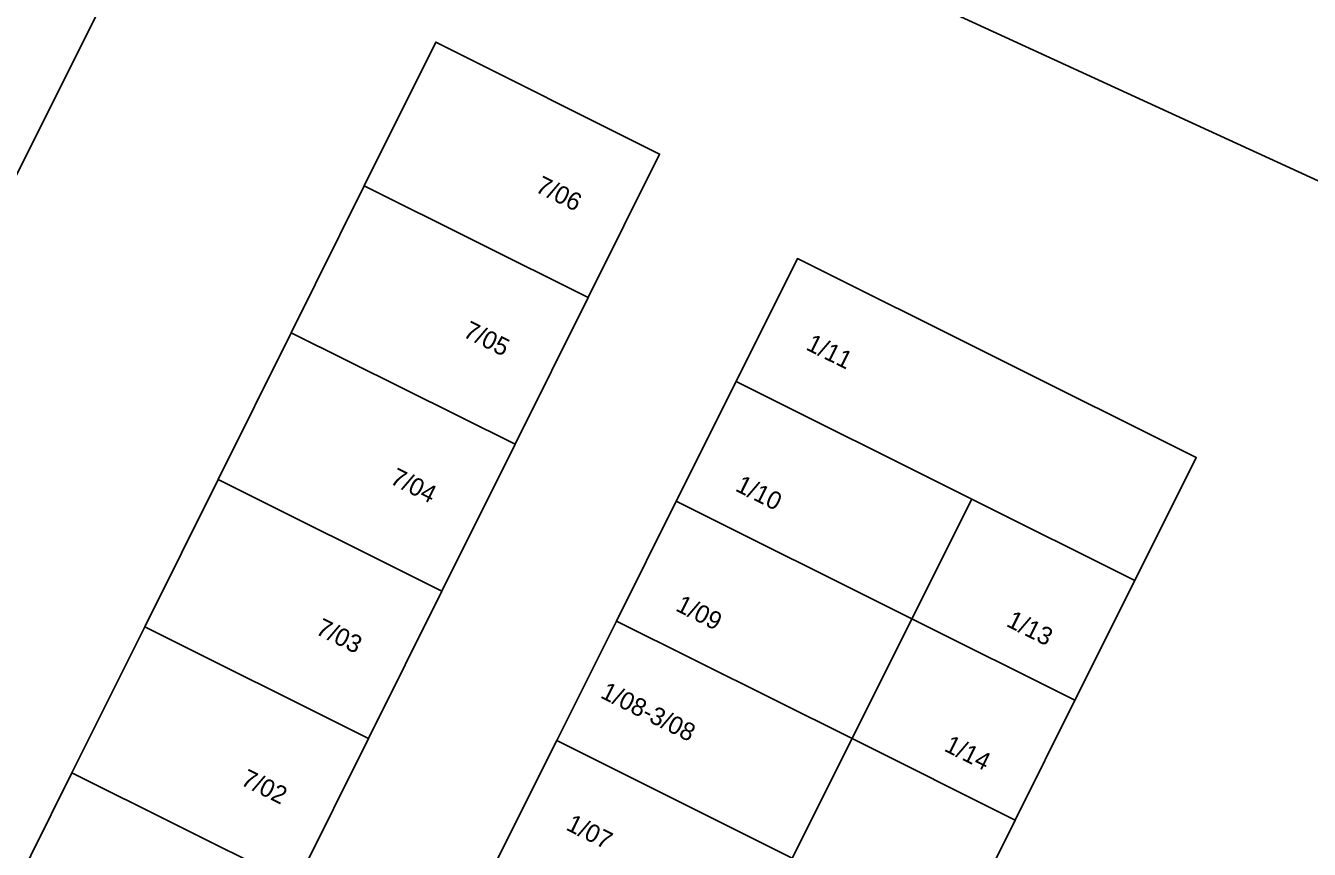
# Model space of a CAD drawing. Extents: x 135999 to 138000, y 396000 to 398501.
# Drawn here: x 136106.9 to 136178.9, y 397811.3 to 397857.5 of the extents above; entities that cross this region are included whole.
import ezdxf

# ---------------------------------------------------------------- set-up
doc = ezdxf.new("R2010")
doc.units = 0
for name, color, linetype in [('gg-anno-huisnummerreeks BGT', 7, 'Continuous'), ('gg-bbg-hoofdgebouw', 7, 'Continuous'), ('gg-bbg-tussenscheiding', 7, 'Continuous'), ('gt-grn-vlakafsluiter', 7, 'Continuous')]:
    doc.layers.add(name, color=color, linetype=linetype)

msp = doc.modelspace()

# ---------------------------------------------------------------- linework, layer by layer
at = {"layer": 'gg-bbg-hoofdgebouw'}
for p, q in [((136125.927, 397848.487), (136121.827, 397840.251)), ((136134.379, 397834.002), (136138.479, 397842.238)), ((136121.827, 397840.251), (136117.728, 397832.016)), ((136143.415, 397830.809), (136146.764, 397837.516)), ((136130.28, 397825.767), (136134.379, 397834.002)), ((136117.728, 397832.016), (136113.617, 397823.757)), ((136140.058, 397824.087), (136143.415, 397830.809)), ((136169.113, 397826.357), (136165.76, 397819.644)), ((136126.169, 397817.508), (136130.28, 397825.767)), ((136113.617, 397823.757), (136109.542, 397815.57)), ((136136.713, 397817.389), (136140.058, 397824.087)), ((136165.76, 397819.644), (136162.409, 397812.933)), ((136122.094, 397809.322), (136126.169, 397817.508)), ((136133.363, 397810.68), (136136.713, 397817.389)), ((136162.409, 397812.933), (136159.06, 397806.226))]:
    msp.add_line(p, q, dxfattribs=at)
for points in [[(136089.92, 397885.69), (136117.759, 397871.805), (136106.169, 397848.565), (136099.457, 397851.913)], [(136138.479, 397842.238), (136142.476, 397850.268), (136129.943, 397856.554), (136125.927, 397848.487)], [(136146.764, 397837.516), (136150.208, 397844.412), (136172.556, 397833.252), (136169.113, 397826.357)], [(136109.542, 397815.57), (136101.439, 397799.293), (136113.973, 397793.008)]]:
    msp.add_lwpolyline(points, dxfattribs=at)
at = {"layer": 'gg-bbg-tussenscheiding'}
for p, q in [((136138.479, 397842.238), (136125.927, 397848.487)), ((136134.379, 397834.002), (136121.827, 397840.251)), ((136146.764, 397837.516), (136159.978, 397830.918)), ((136117.728, 397832.016), (136130.28, 397825.767)), ((136143.415, 397830.809), (136156.624, 397824.209)), ((136156.624, 397824.209), (136159.978, 397830.918)), ((136159.978, 397830.918), (136169.113, 397826.357)), ((136126.169, 397817.508), (136113.617, 397823.757)), ((136140.058, 397824.087), (136153.267, 397817.495)), ((136153.267, 397817.495), (136156.624, 397824.209)), ((136156.624, 397824.209), (136165.76, 397819.644)), ((136136.713, 397817.389), (136149.916, 397810.793)), ((136149.916, 397810.793), (136153.267, 397817.495)), ((136153.267, 397817.495), (136162.409, 397812.933)), ((136122.094, 397809.322), (136109.542, 397815.57))]:
    msp.add_line(p, q, dxfattribs=at)
at = {"layer": 'gt-grn-vlakafsluiter'}
msp.add_line((136183.057, 397847.075), (136158.43, 397858.389), dxfattribs=at)

# ---------------------------------------------------------------- texts
at = {"layer": 'gg-anno-huisnummerreeks BGT'}
for s, rotation, p in [('7/06', 333.5, (136135.457, 397848.195)), ('7/05', 333.5, (136131.408, 397840.062)), ('1/11', 333.5, (136150.625, 397839.337)), ('7/04', 333.5, (136127.309, 397831.826)), ('1/10', 333.5, (136146.67, 397831.417)), ('1/09', 333.5, (136143.315, 397824.698)), ('1/13', 333.5, (136161.859, 397823.828)), ('7/03', 333.6, (136123.141, 397823.393)), ('1/08-3/08', 333.5, (136139.1, 397819.821)), ('1/14', 333.5, (136158.368, 397816.838)), ('7/02', 333.6, (136118.943, 397814.936)), ('1/07', 333.5, (136137.177, 397812.408))]:
    msp.add_text(s, height=1, rotation=rotation, dxfattribs=at).set_placement(p)

doc.saveas('drawing.dxf')
